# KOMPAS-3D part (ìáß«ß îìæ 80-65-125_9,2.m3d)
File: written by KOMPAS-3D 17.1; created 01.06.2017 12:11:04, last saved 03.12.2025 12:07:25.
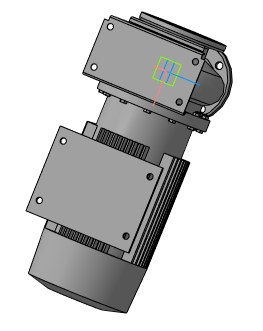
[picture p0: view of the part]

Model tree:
1. Операция без истории:3

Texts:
  ООО АДЛ ГРУПП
